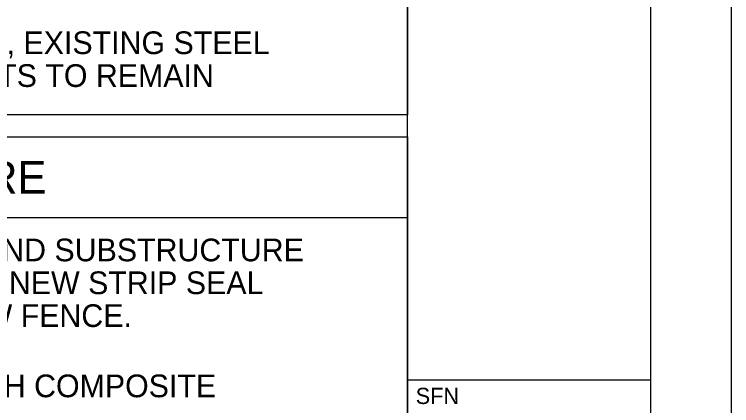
# Model space of a CAD drawing. Extents: x 58.8 to 101.8, y -10 to 13.1.
# Drawn here: x 88.36 to 92.787, y -3.522 to -1.109 of the extents above; entities that cross this region are included whole.
import ezdxf

# ---------------------------------------------------------------- set-up
doc = ezdxf.new("R2010")
doc.units = 0
for name, color, linetype in [('DT_X_Contour_Major', 7, 'Continuous'), ('DT_X_Contour_Minor', 7, 'Continuous'), ('DT_X_Spot_Elev', 7, 'Continuous')]:
    doc.layers.add(name, color=color, linetype=linetype)

msp = doc.modelspace()

# ---------------------------------------------------------------- linework, layer by layer
at = {"layer": 'DT_X_Contour_Major'}
msp.add_line((90.7872, -2.3644), (83.5373, -2.3644), dxfattribs=at)
for points in [[(83.5373, 3.8856), (90.7872, 3.8856), (90.7872, -1.7288), (83.5373, -1.7288)], [(83.5373, -1.8644), (90.7872, -1.8644), (90.7872, -8.3619), (83.5373, -8.3619)]]:
    msp.add_lwpolyline(points, close=True, dxfattribs=at)
at = {"layer": 'DT_X_Contour_Minor'}
msp.add_lwpolyline([(58.7872, -8.8619), (92.7872, -8.8619), (92.7872, 13.1381), (58.7872, 13.1381)], close=True, dxfattribs=at)
at = {"layer": 'DT_X_Spot_Elev'}
for p, q in [((90.7872, -8.3619), (90.7872, 12.6381)), ((90.7872, -3.3619), (92.2872, -3.3619))]:
    msp.add_line(p, q, dxfattribs=at)
msp.add_lwpolyline([(60.2872, 12.6381), (92.2872, 12.6381), (92.2872, -8.3619), (60.2872, -8.3619)], close=True, dxfattribs=at)

# ---------------------------------------------------------------- texts
at = {"layer": 'DT_X_Contour_Major'}
for s, height, p in [('EXISTING DECK TO BE REPLACED, EXISTING STEEL ', 0.14, (85.1914, -1.3542)), ('BEAMS AND SUBSTRUCTURE UNITS TO REMAIN ', 0.14, (85.1914, -1.5567)), ('PROPOSED STRUCTURE', 0.2, (85.3182, -2.2144)), ('DECK SLAB REPLACEMENT AND SUBSTRUCTURE', 0.14, (85.6008, -2.6319)), ('REHABILITATION, INCLUDING NEW STRIP SEAL', 0.14, (85.6008, -2.8344)), ('EXPANSION JOINTS AND NEW FENCE.', 0.14, (85.6008, -3.0369)), ('CONTINUOUS ROLLED STEEL BEAMS WITH COMPOSITE ', 0.14, (84.4873, -3.47)), ('SFN', 0.1, (90.8372, -3.5119))]:
    msp.add_text(s, height=height, dxfattribs=at).set_placement(p)

doc.saveas('drawing.dxf')
